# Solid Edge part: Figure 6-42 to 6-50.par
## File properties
Author: CADCIM
Template: Normal.par
Last saved by: CADCIM
Revision: 8
Application: Solid Edge
Accuracy: 0.99
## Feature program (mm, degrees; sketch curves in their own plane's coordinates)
sketch for "unnamed Protrusion 1" plane through (0, 0, 0) normal (0, 0, 1) x-axis (1, 0, 0)
  line (-87.5, -85) -> (87.5, -85)
  line (87.5, -85) -> (87.5, 85)
  line (87.5, 85) -> (-87.5, 85)
  line (-87.5, 85) -> (-87.5, -85)
extrude "unnamed Protrusion 1" add finite 15.875 along +normal
sketch for "unnamed Cutout 1" plane through (0, 0, 15.875) normal (0, 0, 1) x-axis (1, 0, 0)
  circle centre (-62.5, -60) radius 7
  dimension = 60
  dimension (linear) = 60
  dimension (linear) = 62.5
extrude "unnamed Cutout 1" cut through along -normal
pattern "unnamed Pattern 1" of "unnamed Cutout 1"
extrude "unnamed Cutout 2" cut through
extrude "unnamed Cutout 3" cut through
extrude "unnamed Cutout 4" cut through
extrude "unnamed Cutout 5" cut through
extrude "unnamed Cutout 6" cut through
extrude "unnamed Cutout 7" cut through
extrude "unnamed Cutout 8" cut through
extrude "unnamed Cutout 9" cut through
extrude "unnamed Cutout 10" cut through
extrude "unnamed Cutout 11" cut through
extrude "unnamed Cutout 12" cut through
extrude "unnamed Cutout 13" cut through
extrude "unnamed Cutout 14" cut through
extrude "unnamed Cutout 15" cut through
extrude "unnamed Cutout 16" cut through
extrude "unnamed Cutout 17" cut through
extrude "unnamed Cutout 18" cut through
extrude "unnamed Cutout 19" cut through
extrude "unnamed Cutout 20" cut through
extrude "unnamed Cutout 21" cut through
extrude "unnamed Cutout 22" cut through
extrude "unnamed Cutout 23" cut through
extrude "unnamed Cutout 24" cut through
extrude "unnamed Cutout 25" cut through
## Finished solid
Body 1: solid body, 36 faces, 82 edges, 28 vertices.
  Faces by surface: cylinder 25, plane 11
  Edges by curve: circle 50, line 32
Bounding box of the edges (mm): 175.000 x 170.000 x 15.875, from (-87.5, -85, 0) to (87.5, 85, 15.875).
Cylindrical faces by radius (mm): R7 x25
Planar faces by outward normal: +x 6, +y 1, +z 1, -x 1, -y 1, -z 1
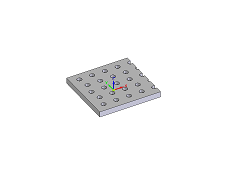
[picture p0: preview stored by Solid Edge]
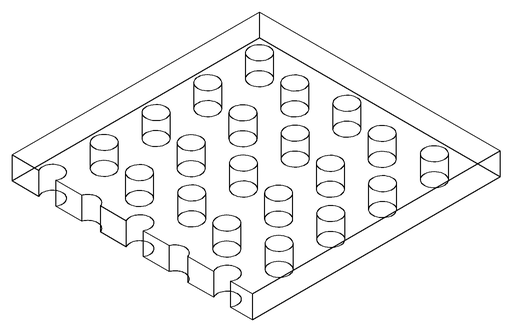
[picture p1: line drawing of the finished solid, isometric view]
